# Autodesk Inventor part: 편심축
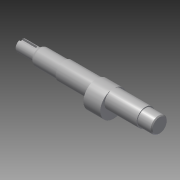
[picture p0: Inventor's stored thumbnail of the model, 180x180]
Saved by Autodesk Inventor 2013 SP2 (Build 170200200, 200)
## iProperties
Created: 2017-08
Part Number: 편심축
Material: 강철, 연강
Document SubType Name: Modeling
Designer: mduedu
Density: 1 g/cm^3
Author: mduedu
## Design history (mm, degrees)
sketch "스케치1"
  geometry: L1 (0, 0)-(156, 0); L2 (156, 0)-(156, 8.5); L3 (156, 8.5)-(141, 8.5); L4 (141, 8.5)-(141, 9.5); L5 (141, 9.5)-(55, 9.5); L6 (55, 9.5)-(55, 8.5); L7 (55, 8.5)-(20, 8.5); L8 (20, 8.5)-(20, 6); L9 (20, 6)-(0, 6); L10 (0, 6)-(0, 0)
  constraints: 20 end point, 6 parallel, 2 collinear, 2 perpendicular, 1 horizontal
  dimensions: "d0" = 156 distance of L1.start L1.end; "d1" = 17 diameter of L3 L1; "d2" = 19 diameter of L5 L1; "d3" = 12 diameter of L9 L1; "d4" = 20 distance of L8.end L9.end; "d5" = 15 distance of L2.end L3.end; "d6" = 86 distance of L4.end L5.end
revolve "회전1" sketch "스케치1" stored, may be unused: angle "d7" = 90 deg
node "작업 평면1"
sketch "스케치2"
  geometry: C1 r 9.5 at (0, 0) reference; C2 r 14 at (0, -4.5); 1 further point
  constraints: 1 centre point, 1 tangent, 1 vertical alignment
  dimensions: "d47" = 28 diameter of C2
extrude "돌출1" join sketch "스케치2" stored distance "d9" = 18; taper "d10" = 0 deg
chamfer "모따기1" distance "d11" = 1; stored, may be unused: second distance "d12" = 2, angle "d13" = 45 deg
node "작업 평면2"
sketch "스케치3"
  geometry: L1 (10, -2)-(-6, -2); L2 (-6, -2)-(-6, 2); L3 (-6, 2)-(10, 2); L4 (10, 2)-(10, -2); L5 (10, 6)-(10, -6) reference; L6 (-10, 8.5)-(-10, -8.5) reference; A1 r 2 centre (-6, 0) between (-6, 2) and (-6, -2); A2 r 2 centre (-6, 0) between (-6, -2) and (-6, 2); 2 further points
  constraints: 8 end point, 4 point on circle, 3 midpoint, 2 centre point, 2 parallel, 1 horizontal, 1 perpendicular
  dimensions: "d16" = 4 distance between parallel lines of L3 L1; "d49" = 18 dimension on A1 L4
extrude "돌출2" cut sketch "스케치3" distance "d18" = 2.5; taper "d19" = 0 deg
chamfer "모따기2" distance "d20" = 1; stored, may be unused: second distance "d21" = 2, angle "d22" = 45 deg
chamfer "모따기4" distance "d39" = 1.82; stored, may be unused: second distance "d40" = 2, angle "d41" = 30 deg
fillet "모깎기4" dims "d45" = 2
hole "구멍1" diameter "d29" = 3.242; stored, may be unused: countersink angle "d33" = 90 deg, drill point angle "d35" = 118 deg; dims "d30" = 8, "d31" = 4, "d32" = 2, "d34" = 10, "d36" = 10, "d37" = 10
node "솔리드1"
node "절단 모서리 투영1"
